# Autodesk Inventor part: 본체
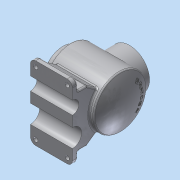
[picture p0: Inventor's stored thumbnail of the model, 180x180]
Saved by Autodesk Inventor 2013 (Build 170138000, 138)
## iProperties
Created: 2018-08
Part Number: 본체
Material: 알루미늄 6061
Document SubType Name: Modeling
Designer: dgall
Density: 2.71 g/cm^3
Mass: 1828.71 g
Surface Area: 1089.44 cm^2
Volume: 674.802 cm^3
Author: dgall
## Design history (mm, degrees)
sketch "스케치4"
  geometry: L1 (0, 0)-(120, 0); L2 (0, 27)-(22, 27); L3 (22, 27)-(22, 40); L4 (22, 40)-(102.163, 40); L5 (102.163, 40)-(102.163, 0); L6 (0, 27)-(0, 38); L7 (0, 38)-(12, 38); L8 (12, 38)-(12, 50); L9 (12, 50)-(108.671, 50); A1 r 106 centre (4, 0) between (110, 0) and (102.163, 40); A2 r 116 centre (4, 0) between (120, 0) and (108.671, 50)
  constraints: 18 end point, 6 parallel, 4 point on circle, 3 point on line, 2 centre point, 2 perpendicular, 1 coincident, 1 horizontal, 1 vertical alignment
  dimensions: "d31" = 80 diameter of L4 L1; "d33" = 116 radius of A2; "d34" = 10 radial gap between concentric circles of A2 A1; "d35" = 100 diameter of L9 L1; "d37" = 76 diameter of L7 L1; "d38" = 54 diameter of L2 L1; "d39" = 12 distance between parallel lines of L8 L6; "d40" = 22 distance between parallel lines of L6 L3; "d41" = 108 distance from line of L1.end L8
revolve "회전2" sketch "스케치4" stored, may be unused: angle "d42" = 90 deg
sketch "스케치5"
  geometry: L1 (20, -82)-(20, -72); L2 (20, -72)-(100, -72); L3 (100, -72)-(100, -82); L4 (100, -82)-(20, -82); L5 (12, -50)-(12, 50) reference; L6 (12, 50)-(108.671, 50) reference; 1 further point
  constraints: 8 end point, 2 parallel, 1 perpendicular, 1 vertical
  dimensions: "d43" = 80 distance between parallel lines of L1 L3; "d45" = 8 distance between parallel lines of L1 L5; "d47" = 10 distance of L1.start L1.end; "d53" = 82 distance from line of L4 point (0, 0)
extrude "돌출3" join sketch "스케치5" stored distance "d48" = 140; taper "d49" = 0 deg
node "작업 평면3"
sketch "스케치6"
  geometry: L1 (0, 10)-(-140, 10) reference; L2 (0, 0)-(0, 10) reference; L3 (0, 0)-(-140, 0) reference; L4 (-140, 10)-(-140, 0) reference; L5 (-106.081, 47.385)-(-120, 27.506); L6 (-120, 27.506)-(-120, 10); L7 (-33.919, 47.385)-(-20, 27.506); L8 (-20, 27.506)-(-20, 10); L9 (-70, 82)-(-70, 0); A1 r 50 centre (-70, 82) between (-106.081, 47.385) and (-33.919, 47.385) reference; 1 further point
  constraints: 10 end point, 2 perpendicular, 2 point on circle, 2 point on line, 1 midpoint, 2 other
  dimensions: "d50" = 20 distance between parallel lines of L4 L6; "d51" = 35 deg angle of L6 L5; "d52" = 19.87884 vertical distance of L7.start L7.end
extrude "돌출4" join sketch "스케치6" stored distance "d54" = 80; taper "d55" = 0 deg
sketch "스케치7"
  geometry: L1 (-70, 82)-(-70, 0); C1 r 50 at (-70, 82) reference; A1 r 17.5 centre (-92.5, 0) between (-75, 0) and (-110, 0); A2 r 12.5 centre (-42.5, 0) between (-30, 0) and (-55, 0); 2 further points
  constraints: 4 point on circle, 2 centre point, 2 end point, 8 other
  dimensions: "d56" = 22.5 distance from line of A1.centre L1; "d58" = 27.5 distance from line of A2.centre L1; "d59" = 17.5 radius of A1; "d60" = 12.5 radius of A2
extrude "돌출5" cut sketch "스케치7" stored distance "d61" = 80; taper "d62" = 0 deg
node "작업 평면4"
sketch "스케치8"
  geometry: L1 (-12, 50)-(-12, -50) reference; C1 r 27 at (-62, 0); C2 r 38 at (-62, 0); 1 further point
  constraints: 2 centre point, 1 coincident, 1 horizontal alignment
  dimensions: "d64" = 50 distance from line of L1 C1.centre; "d65" = 54 diameter of C1; "d66" = 76 diameter of C2
extrude "돌출6" join sketch "스케치8" stored distance "d67" = 80; taper "d68" = 0 deg
extrude "돌출7" cut sketch "스케치8" distance "d69" = 45; taper "d70" = 0 deg
sketch "스케치9" dims "d71" = 65
  geometry: C1 r 38 at (0, 0) reference; 3 further points
  constraints: 2 horizontal alignment, 1 coincident, 2 other
hole "구멍1" sketch "스케치9" at (-32.5, 0) diameter "d73" = 3.242; stored, may be unused: countersink angle "d77" = 90 deg, drill point angle "d79" = 118 deg; dims "d74" = 8, "d75" = 4, "d76" = 2, "d78" = 10
sketch "스케치10" dims "d83" = 65
  geometry: C1 r 38 at (0, 0) reference; C2 r 27 at (0, 0) reference; 2 further points
  constraints: 2 vertical alignment, 1 coincident, 2 other
hole "구멍2" sketch "스케치10" at (0, 32.5) diameter "d85" = 3.242; stored, may be unused: countersink angle "d89" = 90 deg, drill point angle "d91" = 118 deg; dims "d86" = 8, "d87" = 4, "d88" = 2, "d90" = 10
fillet "모깎기1" dims "d95" = 3
fillet "모깎기2" dims "d96" = 10
fillet "모깎기3" dims "d97" = 3
sketch "스케치11"
  geometry: L1 (67, 123)-(7, 123) reference; L2 (77, 93)-(77, 113) reference; L3 (77, 93)-(-3, 93) reference; L4 (-3, 113)-(-3, 93) reference; C1 r 4 at (7, -7); C2 r 4 at (7, 113); C3 r 4 at (67, 113); C4 r 4 at (67, -7); A1 r 7 centre (7, -7) between (0, -7) and (7, -14) reference; A2 r 7 centre (67, -7) between (67, -14) and (74, -7) reference; A3 r 10 centre (7, 113) between (7, 123) and (-3, 113) reference; A4 r 10 centre (67, 113) between (77, 113) and (67, 123) reference; 1 further point
  constraints: 4 centre point, 4 coincident, 3 equal radius
  dimensions: "d98" = 8 diameter of C3
extrude "돌출8" cut sketch "스케치11" distance "d100" = 45; taper "d101" = 0 deg
fillet "모깎기4" dims "d102" = 3
chamfer "모따기1" distance "d103" = 1; stored, may be unused: second distance "d104" = 2, angle "d105" = 45 deg
node "작업 평면6"
  node "작업 평면5"
sketch "스케치12"
  geometry: C1 r 32.5 at (0, 0); 1 further point
  constraints: 1 centre point, 1 coincident, 1 other
  dimensions: "d107" = 65 diameter of C1
feature "엠보싱1" sketch "스케치12" dims "d109" = 0.5, "d110" = 0
node "솔리드2"
pattern_circular "원형 패턴1" dims angle "d81" = 360 deg
pattern_circular "원형 패턴2" dims angle "d93" = 360 deg
node "투영된 루프3"
node "투영된 루프4"
other parameters: "d63" = 65, "d106" = 15
